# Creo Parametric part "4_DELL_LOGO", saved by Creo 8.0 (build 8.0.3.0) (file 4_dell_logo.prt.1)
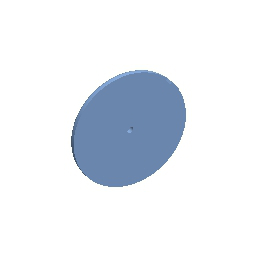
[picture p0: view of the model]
Units: millimeter Newton Second (mmNs); MM, TONNE, SECS

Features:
  1. coordinate system
  2. datum plane "DTM2"
  3. datum plane "DTM3"
  4. datum plane "DTM4"
  5. datum plane "DTM1"
  6. datum plane "DTM6"
  7. protrusion
  8. datum plane "DTM5"
  9. round
  10. curve
  11. protrusion
  12. cut

Other named items: CS0

Layers: 0_ALL_AXIS, 0_ALL_CSYS, 0_ALL_CURVES, 0_ALL_PLANES, 0_ALL_POINTS, 0_ALL_SURFS, DELL_LOGO

Surfaces: 36 plane, 6 cylinder, 4 torus, 1 tabulated cylinder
